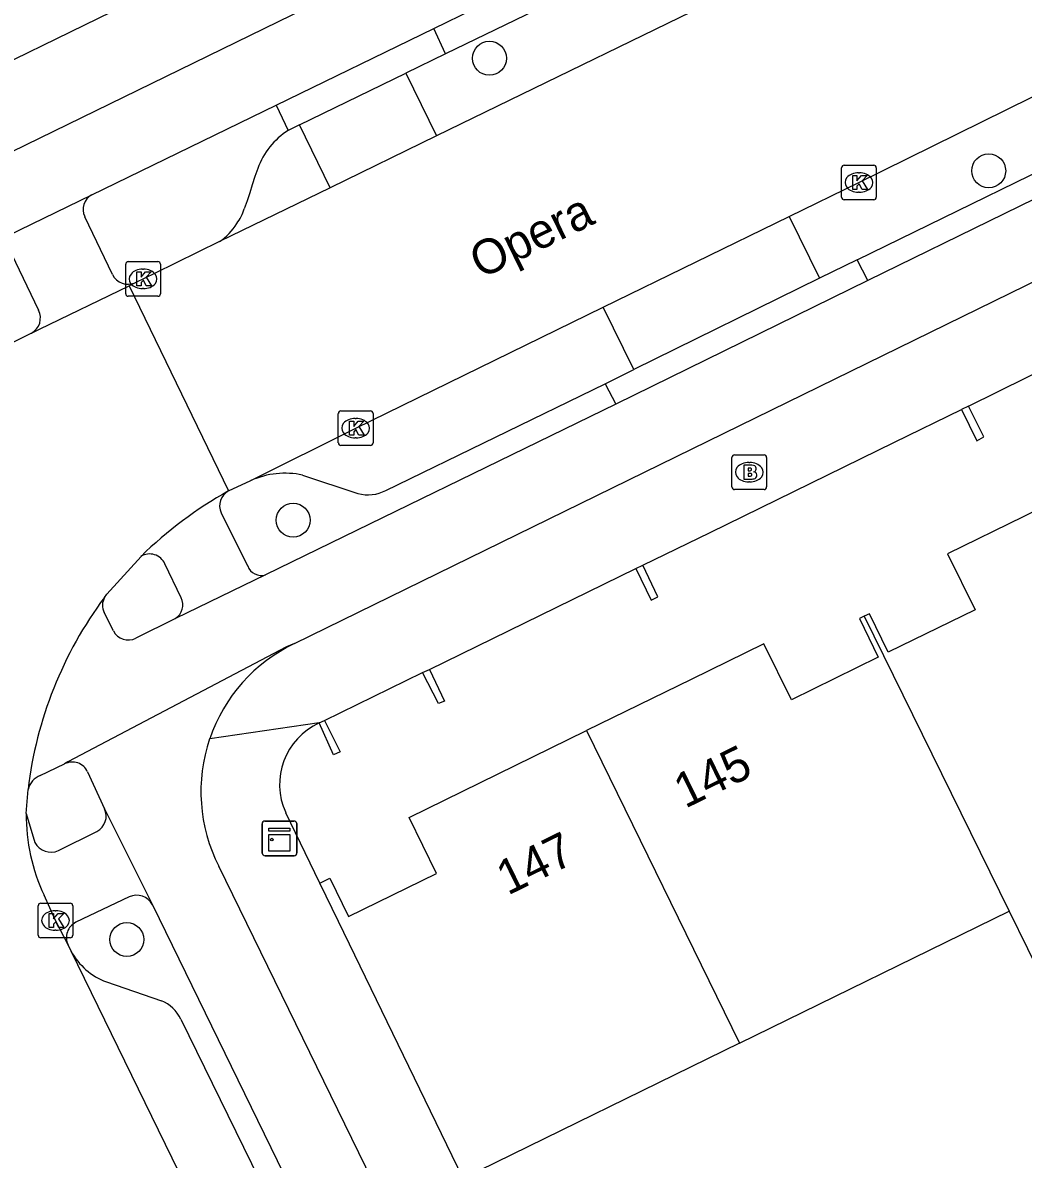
# Model space of a CAD drawing. Extents: x 160457 to 162082, y 388340 to 389736.
# Drawn here: x 160879.52 to 160908.38, y 389051.52 to 389084.3 of the extents above; entities that cross this region are included whole.
import ezdxf

# ---------------------------------------------------------------- set-up
doc = ezdxf.new("R2010")
doc.units = 0
for name, color, linetype in [('IMGEO_Boom', 7, 'Continuous'), ('IMGEO_Brandkraan', 7, 'Continuous'), ('IMGEO_Fietspad_gesloten', 7, 'Continuous'), ('IMGEO_Kast', 7, 'Continuous'), ('IMGEO_Kolk', 7, 'Continuous'), ('IMGEO_Openbare_ruimte_label', 7, 'Continuous'), ('IMGEO_Pand', 7, 'Continuous'), ('IMGEO_Pand_nummerreeks', 7, 'Continuous'), ('IMGEO_Parkeervlak_open', 7, 'Continuous'), ('IMGEO_Rijbaan_lokaal_gesloten', 7, 'Continuous'), ('IMGEO_Verkeerseiland_open', 7, 'Continuous'), ('IMGEO_Voetpad_open', 7, 'Continuous')]:
    doc.layers.add(name, color=color, linetype=linetype)

msp = doc.modelspace()

# ---------------------------------------------------------------- linework, layer by layer
at = {"layer": 'IMGEO_Boom'}
for centre in [(160892.98, 389083.274), (160907.384, 389080.029), (160887.318, 389069.953), (160882.521, 389057.859)]:
    msp.add_circle(centre, 0.489, dxfattribs=at)
at = {"layer": 'IMGEO_Brandkraan'}
for p, q in [((160900.051, 389071.837), (160900.903, 389071.837)), ((160899.976, 389070.911), (160899.976, 389071.763)), ((160900.464, 389071.617), (160900.489, 389071.617)), ((160900.977, 389071.763), (160900.977, 389070.911)), ((160900.903, 389070.837), (160900.051, 389070.837)), ((160900.487, 389071.057), (160900.462, 389071.057))]:
    msp.add_line(p, q, dxfattribs=at)
for points in [[(160900.051, 389071.837), (160900.903, 389071.837)], [(160899.976, 389070.911), (160899.976, 389071.763)], [(160900.324, 389071.537), (160900.324, 389071.137), (160900.537, 389071.137)], [(160900.555, 389071.537), (160900.324, 389071.537)], [(160900.503, 389071.456), (160900.449, 389071.456), (160900.449, 389071.38)], [(160900.977, 389071.763), (160900.977, 389070.911)], [(160900.449, 389071.38), (160900.502, 389071.38)], [(160900.511, 389071.304), (160900.449, 389071.304), (160900.449, 389071.223)], [(160900.449, 389071.223), (160900.511, 389071.223)], [(160900.903, 389070.837), (160900.051, 389070.837)]]:
    msp.add_lwpolyline(points, dxfattribs=at)
for centre, radius, start, end in [((160900.053, 389071.761), 0.0765, 91.552, 178.448), ((160900.053, 389071.761), 0.0765, 91.552, 178.448), ((160900.901, 389071.761), 0.0765, 1.552, 88.448), ((160900.901, 389071.761), 0.0765, 1.552, 88.448), ((160900.504, 389071.418), 0.0379, 267.8285, 90.9355), ((160900.559, 389071.392), 0.145, 59.4692, 91.5367), ((160900.584, 389071.439), 0.0922, 285.5137, 58.1501), ((160900.512, 389071.263), 0.0404, 269.8759, 90.5077), ((160900.543, 389071.388), 0.251, 268.6676, 293.5347), ((160900.589, 389071.247), 0.105, 301.3115, 78.989), ((160900.053, 389070.913), 0.0765, 181.552, 268.448), ((160900.053, 389070.913), 0.0765, 181.552, 268.448), ((160900.901, 389070.913), 0.0765, 271.552, 358.448), ((160900.901, 389070.913), 0.0765, 271.552, 358.448)]:
    msp.add_arc(centre, radius, start, end, dxfattribs=at)
for centre, major_axis, ratio, start_param, end_param in [((160900.463, 389071.337), (-0.387, 0.002), 0.722429, 4.712389, 7.853982), ((160900.488, 389071.337), (-0.39, 0.002), 0.717154, 1.570796, 4.712389)]:
    msp.add_ellipse(centre, major_axis=major_axis, ratio=ratio, start_param=start_param, end_param=end_param, dxfattribs=at)
at = {"layer": 'IMGEO_Fietspad_gesloten'}
for points in [[(160887.362, 389066.396), (160952.948, 389098.503), (160952.979, 389098.518), (161000, 389121.514), (161017.317, 389129.87), (161019.165, 389130.759)], [(160945.498, 389112.928), (160870.289, 389076.234)], [(160891.38, 389084.132), (160903.962, 389090.272)], [(160886.826, 389081.919), (160891.38, 389084.132)], [(160881.51, 389079.336), (160886.826, 389081.919)], [(160911.76, 389080.708), (160903.897, 389076.869)], [(160878.495, 389077.876), (160878.733, 389077.992), (160881.51, 389079.336)], [(160903.897, 389076.869), (160896.629, 389073.3)], [(160896.629, 389073.3), (160886.522, 389068.375)], [(160886.522, 389068.375), (160883.92, 389067.118)], [(160882.135, 389066.762), (160881.869, 389067.29)], [(160883.92, 389067.118), (160882.783, 389066.551)], [(160887.362, 389066.396), (160887.13, 389066.302), (160880.823, 389062.983), (160880.727, 389062.923)], [(160880.025, 389062.593), (160880.727, 389062.923)], [(160881.39, 389062.694), (160881.873, 389061.632)], [(160881.873, 389061.632), (160883.261, 389058.862)], [(160947.207, 388933.03), (160943.921, 388939.826), (160914.477, 389000), (160885.175, 389059.974)], [(160883.261, 389058.862), (160892.163, 389040.604)]]:
    msp.add_lwpolyline(points, dxfattribs=at)
for centre, radius, start, end in [((160882.276, 389067.5), 0.458, 150.3125, 207.3278), ((160882.565, 389066.982), 0.483, 207.1297, 296.7981), ((160889.388, 389062.123), 4.729, 115.364, 161.1958), ((160889.39, 389062.123), 4.732, 161.2104, 207.0118), ((160880.951, 389062.497), 0.481, 24.1372, 117.753), ((160880.269, 389062.022), 0.621, 113.191, 164.2356)]:
    msp.add_arc(centre, radius, start, end, dxfattribs=at)
at = {"layer": 'IMGEO_Kast'}
for p, q in [((160886.425, 389060.353), (160886.425, 389061.194)), ((160886.425, 389061.194), (160886.425, 389060.353)), ((160886.5, 389061.278), (160887.341, 389061.278)), ((160887.341, 389061.278), (160886.5, 389061.278)), ((160887.425, 389061.203), (160887.425, 389060.362)), ((160887.425, 389060.362), (160887.425, 389061.203)), ((160887.35, 389060.278), (160886.509, 389060.278)), ((160886.509, 389060.278), (160887.35, 389060.278))]:
    msp.add_line(p, q, dxfattribs=at)
for points in [[(160886.62, 389061.068), (160887.22, 389061.068), (160887.22, 389060.983), (160886.62, 389060.983), (160886.62, 389061.068)], [(160886.62, 389060.893), (160887.22, 389060.893), (160887.22, 389060.404), (160886.62, 389060.404), (160886.62, 389060.893)]]:
    msp.add_lwpolyline(points, dxfattribs=at)
msp.add_circle((160886.704, 389060.742), 0.0377, dxfattribs=at)
for centre, start, end in [((160886.503, 389061.2), 92.4484, 184.2845), ((160886.503, 389061.2), 92.4484, 184.2845), ((160887.347, 389061.2), 2.4484, 94.2845), ((160887.347, 389061.2), 2.4484, 94.2845), ((160886.503, 389060.356), 182.4484, 274.2845), ((160886.503, 389060.356), 182.4484, 274.2845), ((160887.347, 389060.356), 272.4484, 4.2845), ((160887.347, 389060.356), 272.4484, 4.2845)]:
    msp.add_arc(centre, 0.0779, start, end, dxfattribs=at)
at = {"layer": 'IMGEO_Kolk'}
for p, q in [((160903.14, 389079.265), (160903.14, 389080.117)), ((160903.215, 389080.191), (160904.067, 389080.191)), ((160903.628, 389079.971), (160903.653, 389079.971)), ((160904.141, 389080.117), (160904.141, 389079.265)), ((160903.651, 389079.411), (160903.626, 389079.411)), ((160904.067, 389079.191), (160903.215, 389079.191)), ((160882.564, 389077.411), (160883.416, 389077.411)), ((160882.489, 389076.485), (160882.489, 389077.337)), ((160882.977, 389077.191), (160883.002, 389077.191)), ((160883.49, 389077.337), (160883.49, 389076.485)), ((160883.416, 389076.411), (160882.564, 389076.411)), ((160883, 389076.631), (160882.975, 389076.631)), ((160888.697, 389073.106), (160889.549, 389073.106)), ((160888.622, 389072.18), (160888.622, 389073.032)), ((160889.11, 389072.886), (160889.135, 389072.886)), ((160889.623, 389073.032), (160889.623, 389072.18)), ((160889.549, 389072.106), (160888.697, 389072.106)), ((160889.133, 389072.326), (160889.108, 389072.326)), ((160879.962, 389057.982), (160879.962, 389058.834)), ((160880.037, 389058.908), (160880.889, 389058.908)), ((160880.45, 389058.688), (160880.475, 389058.688)), ((160880.963, 389058.834), (160880.963, 389057.982)), ((160880.473, 389058.128), (160880.448, 389058.128)), ((160880.889, 389057.908), (160880.037, 389057.908))]:
    msp.add_line(p, q, dxfattribs=at)
for points in [[(160903.14, 389079.265), (160903.14, 389080.117)], [(160903.215, 389080.191), (160904.067, 389080.191)], [(160904.141, 389080.117), (160904.141, 389079.265)], [(160903.461, 389079.891), (160903.584, 389079.891), (160903.584, 389079.74), (160903.714, 389079.891), (160903.878, 389079.891), (160903.732, 389079.74), (160903.885, 389079.491), (160903.733, 389079.491), (160903.648, 389079.655), (160903.584, 389079.588), (160903.584, 389079.491), (160903.461, 389079.491), (160903.461, 389079.891)], [(160904.067, 389079.191), (160903.215, 389079.191)], [(160882.564, 389077.411), (160883.416, 389077.411)], [(160882.489, 389076.485), (160882.489, 389077.337)], [(160882.81, 389077.111), (160882.933, 389077.111), (160882.933, 389076.96), (160883.063, 389077.111), (160883.227, 389077.111), (160883.081, 389076.96), (160883.234, 389076.711), (160883.082, 389076.711), (160882.997, 389076.875), (160882.933, 389076.808), (160882.933, 389076.711), (160882.81, 389076.711), (160882.81, 389077.111)], [(160883.49, 389077.337), (160883.49, 389076.485)], [(160883.416, 389076.411), (160882.564, 389076.411)], [(160888.697, 389073.106), (160889.549, 389073.106)], [(160888.622, 389072.18), (160888.622, 389073.032)], [(160888.943, 389072.806), (160889.066, 389072.806), (160889.066, 389072.655), (160889.196, 389072.806), (160889.36, 389072.806), (160889.214, 389072.655), (160889.367, 389072.406), (160889.215, 389072.406), (160889.13, 389072.57), (160889.066, 389072.503), (160889.066, 389072.406), (160888.943, 389072.406), (160888.943, 389072.806)], [(160889.623, 389073.032), (160889.623, 389072.18)], [(160889.549, 389072.106), (160888.697, 389072.106)], [(160879.962, 389057.982), (160879.962, 389058.834)], [(160880.037, 389058.908), (160880.889, 389058.908)], [(160880.963, 389058.834), (160880.963, 389057.982)], [(160880.283, 389058.608), (160880.406, 389058.608), (160880.406, 389058.457), (160880.536, 389058.608), (160880.7, 389058.608), (160880.554, 389058.457), (160880.707, 389058.208), (160880.555, 389058.208), (160880.47, 389058.372), (160880.406, 389058.305), (160880.406, 389058.208), (160880.283, 389058.208), (160880.283, 389058.608)], [(160880.889, 389057.908), (160880.037, 389057.908)]]:
    msp.add_lwpolyline(points, dxfattribs=at)
for centre, start, end in [((160903.217, 389080.115), 91.552, 178.448), ((160903.217, 389080.115), 91.552, 178.448), ((160904.065, 389080.115), 1.552, 88.448), ((160904.065, 389080.115), 1.552, 88.448), ((160903.217, 389079.267), 181.552, 268.448), ((160903.217, 389079.267), 181.552, 268.448), ((160904.065, 389079.267), 271.552, 358.448), ((160904.065, 389079.267), 271.552, 358.448), ((160882.566, 389077.335), 91.552, 178.448), ((160882.566, 389077.335), 91.552, 178.448), ((160883.414, 389077.335), 1.552, 88.448), ((160883.414, 389077.335), 1.552, 88.448), ((160882.566, 389076.487), 181.552, 268.448), ((160882.566, 389076.487), 181.552, 268.448), ((160883.414, 389076.487), 271.552, 358.448), ((160883.414, 389076.487), 271.552, 358.448), ((160888.699, 389073.03), 91.552, 178.448), ((160888.699, 389073.03), 91.552, 178.448), ((160889.547, 389073.03), 1.552, 88.448), ((160889.547, 389073.03), 1.552, 88.448), ((160888.699, 389072.182), 181.552, 268.448), ((160888.699, 389072.182), 181.552, 268.448), ((160889.547, 389072.182), 271.552, 358.448), ((160889.547, 389072.182), 271.552, 358.448), ((160880.039, 389058.832), 91.552, 178.448), ((160880.039, 389058.832), 91.552, 178.448), ((160880.887, 389058.832), 1.552, 88.448), ((160880.887, 389058.832), 1.552, 88.448), ((160880.039, 389057.984), 181.552, 268.448), ((160880.039, 389057.984), 181.552, 268.448), ((160880.887, 389057.984), 271.552, 358.448), ((160880.887, 389057.984), 271.552, 358.448)]:
    msp.add_arc(centre, 0.0765, start, end, dxfattribs=at)
for centre, major_axis, ratio, start_param, end_param in [((160903.627, 389079.691), (-0.387, 0.002), 0.722429, 4.712389, 7.853982), ((160903.652, 389079.691), (-0.39, 0.002), 0.717154, 1.570796, 4.712389), ((160882.976, 389076.911), (-0.387, 0.002), 0.722429, 4.712389, 7.853982), ((160883.001, 389076.911), (-0.39, 0.002), 0.717154, 1.570796, 4.712389), ((160889.109, 389072.606), (-0.387, 0.002), 0.722429, 4.712389, 7.853982), ((160889.134, 389072.606), (-0.39, 0.002), 0.717154, 1.570796, 4.712389), ((160880.449, 389058.408), (-0.387, 0.002), 0.722429, 4.712389, 7.853982), ((160880.474, 389058.408), (-0.39, 0.002), 0.717154, 1.570796, 4.712389)]:
    msp.add_ellipse(centre, major_axis=major_axis, ratio=ratio, start_param=start_param, end_param=end_param, dxfattribs=at)
at = {"layer": 'IMGEO_Pand'}
for points in [[(160906.6, 389073.147), (160907.041, 389072.241), (160907.243, 389072.359), (160906.798, 389073.245)], [(160906.798, 389073.245), (160906.6, 389073.147)], [(160911.318, 389071.49), (160908.401, 389070.062), (160906.199, 389068.984), (160906.991, 389067.368), (160904.487, 389066.143), (160903.942, 389067.257), (160903.795, 389067.185)], [(160897.208, 389068.559), (160897.647, 389067.645), (160897.84, 389067.741), (160897.404, 389068.653)], [(160897.208, 389068.559), (160897.404, 389068.653)], [(160903.795, 389067.185), (160903.654, 389067.116), (160904.199, 389066.001), (160901.693, 389064.775), (160900.901, 389066.391), (160898.798, 389065.362), (160895.783, 389063.886)], [(160903.795, 389067.185), (160907.97, 389058.678)], [(160891.256, 389065.651), (160891.68, 389064.735), (160891.508, 389064.662), (160891.048, 389065.557)], [(160891.048, 389065.557), (160891.256, 389065.651)], [(160888.223, 389064.178), (160888.676, 389063.277), (160888.483, 389063.184), (160888.073, 389064.105)], [(160888.073, 389064.105), (160888.223, 389064.178)], [(160888.087, 389059.484), (160888.375, 389059.625), (160888.915, 389058.52), (160891.456, 389059.764), (160890.664, 389061.38), (160895.783, 389063.886)], [(160895.783, 389063.886), (160900.192, 389054.871)], [(160907.97, 389058.678), (160910.614, 389053.292), (160912.859, 389054.391), (160913.363, 389055.862), (160912.195, 389058.241), (160913.362, 389058.812), (160912.369, 389060.837), (160915.731, 389062.476)], [(160892.225, 389050.972), (160888.627, 389058.379), (160888.087, 389059.484)], [(160900.192, 389054.871), (160907.97, 389058.678)], [(160900.192, 389054.871), (160892.225, 389050.972)]]:
    msp.add_lwpolyline(points, dxfattribs=at)
at = {"layer": 'IMGEO_Parkeervlak_open'}
for points in [[(160904.312, 389089.517), (160900.033, 389087.43), (160891.713, 389083.404)], [(160891.713, 389083.404), (160890.574, 389082.849)], [(160887.503, 389081.352), (160890.574, 389082.849)], [(160890.574, 389082.849), (160891.458, 389081.036)], [(160887.503, 389081.352), (160887.178, 389081.194)], [(160888.387, 389079.541), (160887.503, 389081.352)], [(160903.59, 389077.465), (160911.469, 389081.304)], [(160886.302, 389080.093), (160886.217, 389079.863), (160886.139, 389079.628), (160886.065, 389079.393), (160885.992, 389079.165), (160885.909, 389078.933)], [(160901.626, 389078.709), (160902.501, 389076.929)], [(160903.59, 389077.465), (160902.501, 389076.929)], [(160902.501, 389076.929), (160897.145, 389074.296)], [(160897.145, 389074.296), (160896.263, 389076.092)], [(160896.319, 389073.89), (160897.145, 389074.296)], [(160889.991, 389070.814), (160896.319, 389073.89)], [(160887.591, 389071.253), (160889.188, 389070.725)], [(160881.932, 389056.639), (160883.517, 389056.095)], [(160884.079, 389055.566), (160891.546, 389040.305)]]:
    msp.add_lwpolyline(points, dxfattribs=at)
for centre, radius, start, end in [((160888.307, 389079.396), 2.123, 122.1414, 160.8443), ((160884.507, 389079.372), 1.469, 323.8272, 342.6151), ((160884.154, 389079.488), 1.826, 304.6882, 327.4482), ((160887.083, 389068.895), 2.412, 77.8492, 114.0888), ((160889.48, 389071.757), 1.073, 254.2051, 298.444), ((160882.618, 389058.456), 1.943, 208.6154, 249.308), ((160883.082, 389055.07), 1.114, 26.4616, 67.0035)]:
    msp.add_arc(centre, radius, start, end, dxfattribs=at)
at = {"layer": 'IMGEO_Rijbaan_lokaal_gesloten'}
for points in [[(160901.626, 389078.709), (160903.64, 389079.692), (160918.57, 389087.066), (160926.751, 389091.045)], [(160905.927, 389088.093), (160900.911, 389085.639), (160891.458, 389081.036)], [(160891.458, 389081.036), (160888.387, 389079.541)], [(160888.387, 389079.541), (160885.193, 389077.986)], [(160896.263, 389076.092), (160901.626, 389078.709)], [(160885.193, 389077.986), (160883.315, 389077.071), (160882.76, 389076.798)], [(160879.769, 389075.346), (160879.998, 389075.46), (160882.584, 389076.713)], [(160882.76, 389076.798), (160882.584, 389076.713)], [(160882.584, 389076.713), (160885.45, 389070.796)], [(160886.099, 389071.097), (160889.123, 389072.607), (160896.263, 389076.092)], [(160879.769, 389075.346), (160878.538, 389074.733)], [(160885.45, 389070.796), (160886.099, 389071.097)], [(160881.878, 389067.727), (160881.948, 389067.82), (160882.93, 389068.91)], [(160879.618, 389061.496), (160879.672, 389062.191)], [(160880.827, 389057.703), (160880.463, 389058.408), (160880.134, 389059.136)], [(160880.913, 389057.526), (160880.827, 389057.703)], [(160907.915, 389002.343), (160904.445, 389009.463), (160894.513, 389029.747), (160887.316, 389044.404), (160880.913, 389057.526)]]:
    msp.add_lwpolyline(points, dxfattribs=at)
for centre, radius, start, end in [((160891.42, 389060.192), 12.169, 119.3807, 134.2426), ((160891.118, 389060.838), 11.526, 143.2911, 173.2561), ((160884.97, 389061.43), 5.352, 179.2903, 205.3763)]:
    msp.add_arc(centre, radius, start, end, dxfattribs=at)
at = {"layer": 'IMGEO_Verkeerseiland_open'}
for points in [[(160891.713, 389083.404), (160891.38, 389084.132)], [(160886.826, 389081.919), (160887.178, 389081.194)], [(160903.897, 389076.869), (160903.59, 389077.465)], [(160896.319, 389073.89), (160896.629, 389073.3)]]:
    msp.add_lwpolyline(points, dxfattribs=at)
at = {"layer": 'IMGEO_Voetpad_open'}
for points in [[(160868.431, 389077.96), (160937.126, 389111.479)], [(160882.105, 389077.036), (160881.306, 389078.706)], [(160879.194, 389077.636), (160879.971, 389076.01)], [(160906.798, 389073.245), (160912.719, 389076.16)], [(160897.404, 389068.653), (160899.346, 389069.602), (160904.663, 389072.2), (160906.6, 389073.147)], [(160885.239, 389070.165), (160886.006, 389068.634)], [(160884.09, 389067.716), (160883.618, 389068.693)], [(160891.256, 389065.651), (160897.208, 389068.559)], [(160888.223, 389064.178), (160891.048, 389065.557)], [(160888.073, 389064.105), (160884.911, 389063.647)], [(160879.618, 389061.496), (160879.87, 389060.657)], [(160888.087, 389059.484), (160887.104, 389061.518)], [(160880.545, 389060.425), (160881.658, 389060.975)], [(160882.592, 389059.09), (160881.053, 389058.358)]]:
    msp.add_lwpolyline(points, dxfattribs=at)
for centre, radius, start, end in [((160881.743, 389078.913), 0.483, 118.8125, 205.3026), ((160882.556, 389077.258), 0.503, 206.1715, 293.8904), ((160879.537, 389075.779), 0.491, 298.1417, 28.017), ((160885.697, 389070.363), 0.499, 119.6839, 203.3373), ((160883.178, 389068.499), 0.481, 23.8487, 121.14), ((160886.402, 389068.779), 0.421, 200.0806, 286.6118), ((160883.669, 389067.512), 0.467, 302.4256, 25.8355), ((160888.883, 389062.327), 1.954, 114.4894, 204.4423), ((160881.428, 389061.414), 0.496, 297.6632, 26.0959), ((160880.333, 389060.906), 0.526, 208.2981, 293.7659), ((160882.806, 389058.622), 0.515, 27.7986, 114.5625), ((160881.267, 389057.918), 0.489, 115.8997, 206.0275)]:
    msp.add_arc(centre, radius, start, end, dxfattribs=at)

# ---------------------------------------------------------------- texts
at = {"layer": 'IMGEO_Openbare_ruimte_label'}
msp.add_text('Opera', height=1, rotation=25.9757, dxfattribs=at).set_placement((160892.733, 389076.901))
at = {"layer": 'IMGEO_Pand_nummerreeks'}
for s, p in [('145', (160898.628, 389061.627)), ('147', (160893.509, 389059.121))]:
    msp.add_text(s, height=1, rotation=26.0817, dxfattribs=at).set_placement(p)

doc.saveas('drawing.dxf')
